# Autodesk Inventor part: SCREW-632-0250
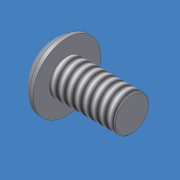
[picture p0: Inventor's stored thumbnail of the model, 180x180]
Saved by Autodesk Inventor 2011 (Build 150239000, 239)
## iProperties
Created: 2007-08
Part Number: SCREW-632-0250
Document SubType Name: Modeling
Material: Stainless Steel
Density: 8.08 g/cm^3
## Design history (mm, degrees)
feature "Base1"
thread "Thread1" dims "d0" = 25.4, "d1" = 0
body "Solid1"
